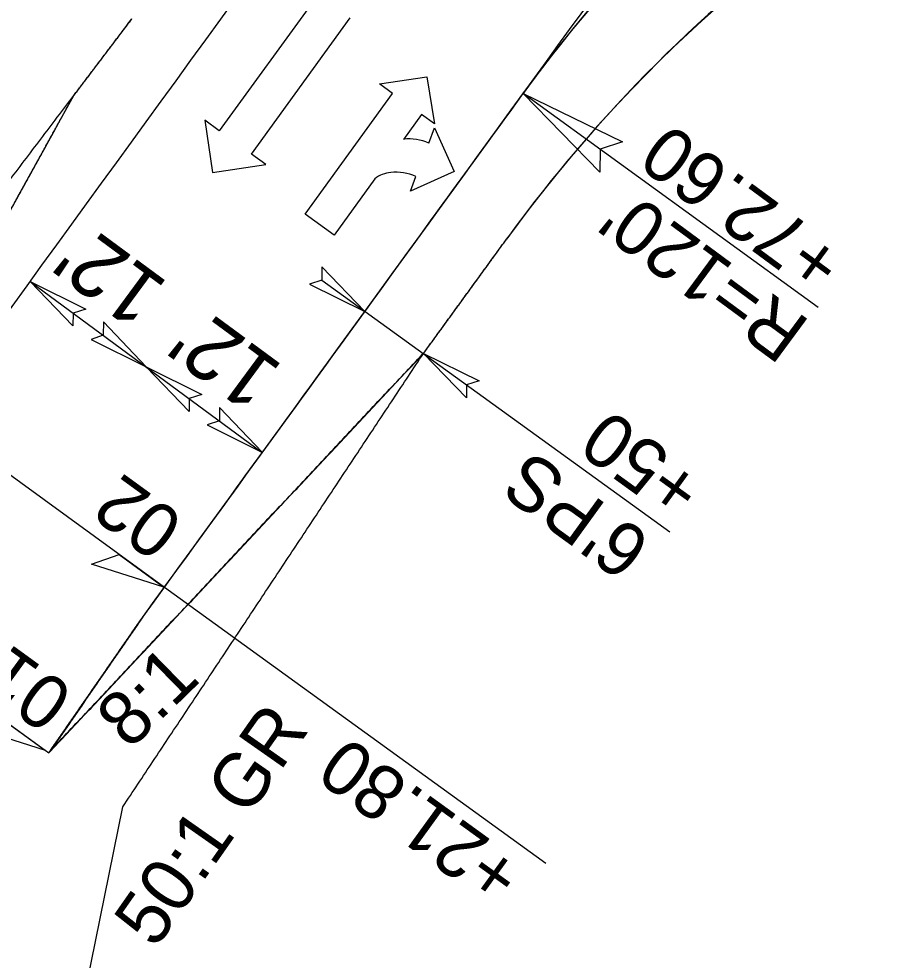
# Model space of a CAD drawing. Extents: x 1183930 to 1185370, y 573068 to 574871.
# Drawn here: x 1184246.9 to 1184319.5, y 573626.5 to 573704.9 of the extents above; entities that cross this region are included whole.
import ezdxf

# ---------------------------------------------------------------- set-up
doc = ezdxf.new("R2010")
doc.units = 0
for name, color, linetype in [('E_NCDOT_Terrain_Model_Contour_Minor', 7, 'Continuous'), ('E_NCDOT_Vertical_Profile_Ground_Line', 7, 'Continuous'), ('P_NCDOT_Horizontal_Alignment', 7, 'Continuous'), ('P_NCDOT_Horizontal_Alignment_Tick_Large', 7, 'Continuous'), ('PC_BEAM', 7, 'Continuous'), ('PC_COLUMN', 7, 'Continuous'), ('PC_OBJECT', 7, 'Continuous'), ('PC_PADFOOTING', 7, 'Continuous'), ('PC_SLAB', 7, 'Continuous')]:
    doc.layers.add(name, color=color, linetype=linetype)

msp = doc.modelspace()

# ---------------------------------------------------------------- linework, layer by layer
for points in [[(1184271.098, 573682.806), (1184275.711, 573680.544), (1184272.115, 573684.258), (1184272.111, 573683.15)], [(1184251.415, 573679.329), (1184247.856, 573683.034), (1184252.488, 573680.739), (1184251.434, 573680.398)], [(1184252.924, 573678.216), (1184257.517, 573675.915), (1184253.953, 573679.66), (1184253.94, 573678.551)], [(1184284.161, 573673.352), (1184280.571, 573677.026), (1184285.223, 573674.77), (1184284.171, 573674.421)], [(1184261.076, 573672.211), (1184257.517, 573675.915), (1184262.149, 573673.62), (1184261.095, 573673.28)], [(1184262.585, 573671.098), (1184267.178, 573668.797), (1184263.614, 573672.541), (1184263.601, 573671.433)]]:
    msp.add_lwpolyline(points, close=True)
at = {"layer": 'E_NCDOT_Terrain_Model_Contour_Minor'}
msp.add_line((1184313.426, 573680.866), (1184288.878, 573698.681), dxfattribs=at)
msp.add_lwpolyline([(1184295.251, 573692.14), (1184288.878, 573698.681), (1184297.142, 573694.66), (1184295.272, 573694.041)], close=True, dxfattribs=at)
at = {"layer": 'E_NCDOT_Vertical_Profile_Ground_Line'}
msp.add_arc((1184384.592, 573616.049), 120, 94.52634, 144.0215, dxfattribs=at)
for points in [[(1184251.486, 573698.511), (1184251.567, 573698.617), (1184251.728, 573698.83), (1184251.969, 573699.149), (1184252.211, 573699.468), (1184252.452, 573699.788), (1184252.694, 573700.107), (1184252.936, 573700.426), (1184253.177, 573700.745), (1184253.419, 573701.065), (1184253.661, 573701.384), (1184253.902, 573701.703), (1184254.144, 573702.022), (1184254.385, 573702.341), (1184254.627, 573702.661), (1184254.869, 573702.98), (1184255.11, 573703.299), (1184255.352, 573703.618), (1184255.593, 573703.938), (1184255.835, 573704.257), (1184256.077, 573704.576), (1184256.238, 573704.789), (1184256.318, 573704.895)], [(1184251.486, 573698.511), (1184251.567, 573698.617), (1184251.728, 573698.83), (1184251.969, 573699.149), (1184252.211, 573699.468), (1184252.452, 573699.788), (1184252.694, 573700.107), (1184252.936, 573700.426), (1184253.177, 573700.745), (1184253.419, 573701.065), (1184253.661, 573701.384), (1184253.902, 573701.703), (1184254.144, 573702.022), (1184254.385, 573702.341), (1184254.627, 573702.661), (1184254.869, 573702.98), (1184255.11, 573703.299), (1184255.352, 573703.618), (1184255.593, 573703.938), (1184255.835, 573704.257), (1184256.077, 573704.576), (1184256.238, 573704.789), (1184256.318, 573704.895)], [(1184251.486, 573698.511), (1184251.567, 573698.617), (1184251.728, 573698.83), (1184251.969, 573699.149), (1184252.211, 573699.468), (1184252.452, 573699.788), (1184252.694, 573700.107), (1184252.936, 573700.426), (1184253.177, 573700.745), (1184253.419, 573701.065), (1184253.661, 573701.384), (1184253.902, 573701.703), (1184254.144, 573702.022), (1184254.385, 573702.341), (1184254.627, 573702.661), (1184254.869, 573702.98), (1184255.11, 573703.299), (1184255.352, 573703.618), (1184255.593, 573703.938), (1184255.835, 573704.257), (1184256.077, 573704.576), (1184256.238, 573704.789), (1184256.318, 573704.895)], [(1184229.343, 573658.378), (1184229.712, 573659.047), (1184230.451, 573660.384), (1184231.559, 573662.391), (1184232.666, 573664.397), (1184233.774, 573666.404), (1184234.881, 573668.41), (1184235.989, 573670.417), (1184237.096, 573672.423), (1184238.203, 573674.43), (1184239.311, 573676.436), (1184240.418, 573678.443), (1184241.525, 573680.45), (1184242.632, 573682.456), (1184243.739, 573684.463), (1184244.846, 573686.47), (1184245.953, 573688.477), (1184247.06, 573690.483), (1184248.166, 573692.49), (1184249.273, 573694.497), (1184250.379, 573696.504), (1184251.117, 573697.842), (1184251.486, 573698.511)], [(1184229.343, 573658.378), (1184229.712, 573659.047), (1184230.451, 573660.384), (1184231.559, 573662.391), (1184232.666, 573664.397), (1184233.774, 573666.404), (1184234.881, 573668.41), (1184235.989, 573670.417), (1184237.096, 573672.423), (1184238.203, 573674.43), (1184239.311, 573676.436), (1184240.418, 573678.443), (1184241.525, 573680.45), (1184242.632, 573682.456), (1184243.739, 573684.463), (1184244.846, 573686.47), (1184245.953, 573688.477), (1184247.06, 573690.483), (1184248.166, 573692.49), (1184249.273, 573694.497), (1184250.379, 573696.504), (1184251.117, 573697.842), (1184251.486, 573698.511)], [(1184229.343, 573658.378), (1184229.712, 573659.047), (1184230.451, 573660.384), (1184231.559, 573662.391), (1184232.666, 573664.397), (1184233.774, 573666.404), (1184234.881, 573668.41), (1184235.989, 573670.417), (1184237.096, 573672.423), (1184238.203, 573674.43), (1184239.311, 573676.436), (1184240.418, 573678.443), (1184241.525, 573680.45), (1184242.632, 573682.456), (1184243.739, 573684.463), (1184244.846, 573686.47), (1184245.953, 573688.477), (1184247.06, 573690.483), (1184248.166, 573692.49), (1184249.273, 573694.497), (1184250.379, 573696.504), (1184251.117, 573697.842), (1184251.486, 573698.511)], [(1184280.571, 573677.026), (1184280.686, 573677.185), (1184280.917, 573677.502), (1184281.263, 573677.978), (1184281.608, 573678.454), (1184281.954, 573678.93), (1184282.3, 573679.406), (1184282.645, 573679.882), (1184282.991, 573680.358), (1184283.337, 573680.834), (1184283.682, 573681.31), (1184284.028, 573681.786), (1184284.373, 573682.262), (1184284.719, 573682.738), (1184285.065, 573683.214), (1184285.41, 573683.69), (1184285.756, 573684.166), (1184286.102, 573684.642), (1184286.447, 573685.118), (1184286.793, 573685.594), (1184287.138, 573686.07), (1184287.369, 573686.388), (1184287.484, 573686.547)], [(1184280.571, 573677.026), (1184280.686, 573677.185), (1184280.917, 573677.502), (1184281.263, 573677.978), (1184281.608, 573678.454), (1184281.954, 573678.93), (1184282.3, 573679.406), (1184282.645, 573679.882), (1184282.991, 573680.358), (1184283.337, 573680.834), (1184283.682, 573681.31), (1184284.028, 573681.786), (1184284.373, 573682.262), (1184284.719, 573682.738), (1184285.065, 573683.214), (1184285.41, 573683.69), (1184285.756, 573684.166), (1184286.102, 573684.642), (1184286.447, 573685.118), (1184286.793, 573685.594), (1184287.138, 573686.07), (1184287.369, 573686.388), (1184287.484, 573686.547)], [(1184249.41, 573643.786), (1184249.929, 573644.34), (1184250.968, 573645.448), (1184252.527, 573647.109), (1184254.085, 573648.771), (1184255.644, 573650.432), (1184257.202, 573652.094), (1184258.76, 573653.756), (1184260.318, 573655.418), (1184261.877, 573657.079), (1184263.435, 573658.741), (1184264.993, 573660.403), (1184266.551, 573662.065), (1184268.109, 573663.727), (1184269.667, 573665.39), (1184271.225, 573667.052), (1184272.783, 573668.714), (1184274.34, 573670.376), (1184275.898, 573672.039), (1184277.456, 573673.701), (1184279.014, 573675.364), (1184280.052, 573676.472), (1184280.571, 573677.026)], [(1184249.41, 573643.786), (1184249.929, 573644.34), (1184250.968, 573645.448), (1184252.527, 573647.109), (1184254.085, 573648.771), (1184255.644, 573650.432), (1184257.202, 573652.094), (1184258.76, 573653.756), (1184260.318, 573655.418), (1184261.877, 573657.079), (1184263.435, 573658.741), (1184264.993, 573660.403), (1184266.551, 573662.065), (1184268.109, 573663.727), (1184269.667, 573665.39), (1184271.225, 573667.052), (1184272.783, 573668.714), (1184274.34, 573670.376), (1184275.898, 573672.039), (1184277.456, 573673.701), (1184279.014, 573675.364), (1184280.052, 573676.472), (1184280.571, 573677.026)]]:
    msp.add_open_spline(points, degree=3, dxfattribs=at)
at = {"layer": 'P_NCDOT_Horizontal_Alignment'}
msp.add_line((1184229.343, 573658.378), (1184249.41, 573643.786), dxfattribs=at)
for centre, radius, start, end in [((1124762.272, 616900.028), 73527.16, 323.98763727, 324.09287436), ((1124762.272, 616900.028), 73527.16, 323.98763727, 324.09287436), ((1184385.997, 573628.197), 120, 94.52634, 144.02979), ((1184385.997, 573628.197), 120, 94.52634, 144.02979), ((1124762.272, 616900.028), 73551.16, 323.98763727, 324.06939248), ((1124762.272, 616900.028), 73551.16, 323.98763727, 324.02978658), ((1124762.272, 616900.028), 73551.16, 323.98763727, 324.02978658)]:
    msp.add_arc(centre, radius, start, end, dxfattribs=at)
msp.add_open_spline([(1184249.41, 573643.786), (1184249.538, 573643.971), (1184249.793, 573644.342), (1184250.177, 573644.898), (1184250.561, 573645.454), (1184250.944, 573646.009), (1184251.328, 573646.565), (1184251.711, 573647.121), (1184252.095, 573647.677), (1184252.479, 573648.233), (1184252.862, 573648.788), (1184253.246, 573649.344), (1184253.629, 573649.9), (1184254.013, 573650.456), (1184254.396, 573651.012), (1184254.78, 573651.567), (1184255.163, 573652.123), (1184255.547, 573652.679), (1184255.931, 573653.235), (1184256.314, 573653.791), (1184256.698, 573654.347), (1184256.953, 573654.717), (1184257.081, 573654.902)], degree=3, dxfattribs=at)
msp.add_open_spline([(1184249.41, 573643.786), (1184249.538, 573643.971), (1184249.793, 573644.342), (1184250.177, 573644.898), (1184250.561, 573645.454), (1184250.944, 573646.009), (1184251.328, 573646.565), (1184251.711, 573647.121), (1184252.095, 573647.677), (1184252.479, 573648.233), (1184252.862, 573648.788), (1184253.246, 573649.344), (1184253.629, 573649.9), (1184254.013, 573650.456), (1184254.396, 573651.012), (1184254.78, 573651.567), (1184255.163, 573652.123), (1184255.547, 573652.679), (1184255.931, 573653.235), (1184256.314, 573653.791), (1184256.698, 573654.347), (1184256.953, 573654.717), (1184257.081, 573654.902)], degree=3, dxfattribs=at)
at = {"layer": 'P_NCDOT_Horizontal_Alignment_Tick_Large'}
msp.add_arc((1184384.592, 573616.049), 120, 94.52634, 144.0215, dxfattribs=at)
msp.add_arc((1184384.592, 573616.049), 120, 94.52634, 144.0215, dxfattribs=at)
for points, degree in [([(1184251.486, 573698.511), (1184251.532, 573698.571), (1184251.69, 573698.781), (1184251.979, 573699.162), (1184252.208, 573699.465), (1184252.453, 573699.789), (1184252.694, 573700.107), (1184252.936, 573700.426), (1184253.177, 573700.745), (1184253.419, 573701.065), (1184253.661, 573701.384), (1184253.902, 573701.703), (1184254.144, 573702.022), (1184254.385, 573702.341), (1184254.627, 573702.661), (1184254.869, 573702.98), (1184255.11, 573703.299), (1184255.351, 573703.617), (1184255.596, 573703.941), (1184255.825, 573704.244), (1184256.114, 573704.625), (1184256.272, 573704.835), (1184256.318, 573704.895)], 2), ([(1184251.486, 573698.511), (1184251.532, 573698.571), (1184251.69, 573698.781), (1184251.979, 573699.162), (1184252.208, 573699.465), (1184252.453, 573699.789), (1184252.694, 573700.107), (1184252.936, 573700.426), (1184253.177, 573700.745), (1184253.419, 573701.065), (1184253.661, 573701.384), (1184253.902, 573701.703), (1184254.144, 573702.022), (1184254.385, 573702.341), (1184254.627, 573702.661), (1184254.869, 573702.98), (1184255.11, 573703.299), (1184255.351, 573703.617), (1184255.596, 573703.941), (1184255.825, 573704.244), (1184256.114, 573704.625), (1184256.272, 573704.835), (1184256.318, 573704.895)], 2), ([(1184224.019, 573662.249), (1184224.477, 573662.853), (1184225.393, 573664.061), (1184226.767, 573665.874), (1184228.141, 573667.687), (1184229.515, 573669.5), (1184230.888, 573671.313), (1184232.262, 573673.126), (1184233.635, 573674.939), (1184235.009, 573676.752), (1184236.382, 573678.565), (1184237.756, 573680.378), (1184239.129, 573682.191), (1184240.502, 573684.004), (1184241.875, 573685.817), (1184243.248, 573687.63), (1184244.621, 573689.444), (1184245.994, 573691.257), (1184247.367, 573693.07), (1184248.74, 573694.884), (1184250.113, 573696.697), (1184251.028, 573697.906), (1184251.486, 573698.511)], 3), ([(1184224.019, 573662.249), (1184224.477, 573662.853), (1184225.393, 573664.061), (1184226.767, 573665.874), (1184228.141, 573667.687), (1184229.515, 573669.5), (1184230.888, 573671.313), (1184232.262, 573673.126), (1184233.635, 573674.939), (1184235.009, 573676.752), (1184236.382, 573678.565), (1184237.756, 573680.378), (1184239.129, 573682.191), (1184240.502, 573684.004), (1184241.875, 573685.817), (1184243.248, 573687.63), (1184244.621, 573689.444), (1184245.994, 573691.257), (1184247.367, 573693.07), (1184248.74, 573694.884), (1184250.113, 573696.697), (1184251.028, 573697.906), (1184251.486, 573698.511)], 3), ([(1184280.571, 573677.026), (1184280.637, 573677.116), (1184280.864, 573677.429), (1184281.277, 573677.998), (1184281.604, 573678.449), (1184281.955, 573678.932), (1184282.299, 573679.406), (1184282.645, 573679.882), (1184282.991, 573680.358), (1184283.337, 573680.834), (1184283.682, 573681.31), (1184284.028, 573681.786), (1184284.373, 573682.262), (1184284.719, 573682.738), (1184285.065, 573683.214), (1184285.41, 573683.69), (1184285.756, 573684.167), (1184286.101, 573684.641), (1184286.451, 573685.124), (1184286.778, 573685.575), (1184287.192, 573686.144), (1184287.418, 573686.456), (1184287.484, 573686.547)], 2), ([(1184280.571, 573677.026), (1184280.637, 573677.116), (1184280.864, 573677.429), (1184281.277, 573677.998), (1184281.604, 573678.449), (1184281.955, 573678.932), (1184282.299, 573679.406), (1184282.645, 573679.882), (1184282.991, 573680.358), (1184283.337, 573680.834), (1184283.682, 573681.31), (1184284.028, 573681.786), (1184284.373, 573682.262), (1184284.719, 573682.738), (1184285.065, 573683.214), (1184285.41, 573683.69), (1184285.756, 573684.167), (1184286.101, 573684.641), (1184286.451, 573685.124), (1184286.778, 573685.575), (1184287.192, 573686.144), (1184287.418, 573686.456), (1184287.484, 573686.547)], 2), ([(1184255.57, 573639.307), (1184255.987, 573639.935), (1184256.821, 573641.192), (1184258.071, 573643.078), (1184259.322, 573644.964), (1184260.572, 573646.849), (1184261.823, 573648.735), (1184263.073, 573650.621), (1184264.323, 573652.507), (1184265.573, 573654.393), (1184266.824, 573656.279), (1184268.074, 573658.165), (1184269.324, 573660.051), (1184270.574, 573661.937), (1184271.824, 573663.823), (1184273.073, 573665.709), (1184274.323, 573667.595), (1184275.573, 573669.481), (1184276.823, 573671.367), (1184278.072, 573673.254), (1184279.322, 573675.14), (1184280.155, 573676.397), (1184280.571, 573677.026)], 3), ([(1184255.57, 573639.307), (1184255.987, 573639.935), (1184256.821, 573641.192), (1184258.071, 573643.078), (1184259.322, 573644.964), (1184260.572, 573646.849), (1184261.823, 573648.735), (1184263.073, 573650.621), (1184264.323, 573652.507), (1184265.573, 573654.393), (1184266.824, 573656.279), (1184268.074, 573658.165), (1184269.324, 573660.051), (1184270.574, 573661.937), (1184271.824, 573663.823), (1184273.073, 573665.709), (1184274.323, 573667.595), (1184275.573, 573669.481), (1184276.823, 573671.367), (1184278.072, 573673.254), (1184279.322, 573675.14), (1184280.155, 573676.397), (1184280.571, 573677.026)], 3)]:
    msp.add_open_spline(points, degree=degree, dxfattribs=at)
at = {"layer": 'PC_BEAM'}
for p, q in [((1184271.809, 573706.912), (1184263.588, 573695.581)), ((1184266.259, 573693.643), (1184274.48, 573704.974)), ((1184276.917, 573699.475), (1184280.85, 573700.073)), ((1184280.85, 573700.073), (1184281.51, 573696.151)), ((1184278.011, 573698.684), (1184276.917, 573699.475)), ((1184270.729, 573688.622), (1184278.011, 573698.684)), ((1184280.417, 573696.942), (1184278.913, 573694.864)), ((1184281.51, 573696.151), (1184280.417, 573696.942)), ((1184263.588, 573695.581), (1184262.374, 573696.462)), ((1184262.374, 573696.462), (1184263.033, 573692.092)), ((1184281.024, 573694.558), (1184281.498, 573695.826)), ((1184281.498, 573695.826), (1184283.144, 573692.191)), ((1184267.473, 573692.762), (1184266.259, 573693.643)), ((1184263.033, 573692.092), (1184267.473, 573692.762)), ((1184283.144, 573692.191), (1184279.508, 573690.545)), ((1184276.538, 573691.584), (1184273.135, 573686.881)), ((1184279.508, 573690.545), (1184279.955, 573691.777)), ((1184273.135, 573686.881), (1184270.729, 573688.622))]:
    msp.add_line(p, q, dxfattribs=at)
for centre, radius, start, end in [((1184279.378, 573690.912), 3.991, 65.6939, 96.5725), ((1184277.982, 573689.828), 2.272, 93.17619, 129.48818), ((1184278.319, 573688.133), 3.991, 65.81271, 96.66627)]:
    msp.add_arc(centre, radius, start, end, dxfattribs=at)
at = {"layer": 'PC_COLUMN'}
for points in [[(1184258.987, 573657.597), (1184252.958, 573659.508), (1184255.246, 573660.317)], [(1184249.137, 573643.985), (1184243.108, 573645.896), (1184245.396, 573646.705)]]:
    msp.add_lwpolyline(points, close=True, dxfattribs=at)
at = {"layer": 'PC_OBJECT'}
for centre, radius, start, end in [((1124762.272, 616900.028), 73527.16, 323.98763727, 324.09287436), ((1184386.112, 573628.356), 120, 94.52634, 144.02979), ((1184384.708, 573616.207), 120, 125.84259, 144.0215), ((1124762.388, 616900.186), 73551.16, 323.98763727, 324.02978658)]:
    msp.add_arc(centre, radius, start, end, dxfattribs=at)
for points in [[(1184251.486, 573698.511), (1184251.497, 573698.525), (1184251.508, 573698.54), (1184251.519, 573698.554), (1184251.664, 573698.747), (1184251.81, 573698.939), (1184251.955, 573699.131), (1184252.101, 573699.323), (1184252.246, 573699.515), (1184252.392, 573699.707), (1184252.537, 573699.899), (1184252.682, 573700.092), (1184252.828, 573700.284), (1184252.973, 573700.476), (1184253.119, 573700.668), (1184253.264, 573700.86), (1184253.41, 573701.052), (1184253.555, 573701.244), (1184253.701, 573701.437), (1184253.846, 573701.629), (1184253.991, 573701.821), (1184254.137, 573702.013), (1184254.282, 573702.205), (1184254.428, 573702.397), (1184254.573, 573702.59), (1184254.719, 573702.782), (1184254.864, 573702.974), (1184255.009, 573703.166), (1184255.155, 573703.358), (1184255.3, 573703.55), (1184255.446, 573703.742), (1184255.737, 573704.127), (1184256.027, 573704.511), (1184256.318, 573704.895)], [(1184244.108, 573685.132), (1184244.132, 573685.175), (1184244.156, 573685.219), (1184244.18, 573685.262), (1184244.277, 573685.438), (1184244.374, 573685.614), (1184244.471, 573685.789), (1184244.567, 573685.965), (1184244.664, 573686.141), (1184244.761, 573686.317), (1184244.858, 573686.492), (1184244.955, 573686.668), (1184245.052, 573686.844), (1184245.149, 573687.019), (1184245.246, 573687.195), (1184245.343, 573687.371), (1184245.44, 573687.547), (1184245.537, 573687.722), (1184245.634, 573687.898), (1184245.731, 573688.074), (1184245.828, 573688.25), (1184245.924, 573688.425), (1184246.021, 573688.601), (1184246.118, 573688.777), (1184246.215, 573688.953), (1184246.312, 573689.128), (1184246.409, 573689.304), (1184246.506, 573689.48), (1184246.603, 573689.655), (1184246.7, 573689.831), (1184246.797, 573690.007), (1184246.894, 573690.183), (1184246.991, 573690.358), (1184247.088, 573690.534), (1184247.184, 573690.71), (1184247.281, 573690.886), (1184247.378, 573691.061), (1184247.475, 573691.237), (1184247.572, 573691.413), (1184247.669, 573691.589), (1184247.766, 573691.764), (1184247.863, 573691.94), (1184247.96, 573692.116), (1184248.057, 573692.292), (1184248.154, 573692.467), (1184248.25, 573692.643), (1184248.347, 573692.819), (1184248.444, 573692.995), (1184248.541, 573693.17), (1184248.638, 573693.346), (1184248.735, 573693.522), (1184248.832, 573693.697), (1184248.929, 573693.873), (1184249.026, 573694.049), (1184249.123, 573694.225), (1184249.22, 573694.4), (1184249.316, 573694.576), (1184249.413, 573694.752), (1184249.51, 573694.928), (1184249.607, 573695.103), (1184249.704, 573695.279), (1184249.801, 573695.455), (1184249.898, 573695.631), (1184249.995, 573695.806), (1184250.092, 573695.982), (1184250.189, 573696.158), (1184250.285, 573696.334), (1184250.686, 573697.059), (1184251.086, 573697.785), (1184251.486, 573698.511)], [(1184280.686, 573677.185), (1184280.802, 573677.343), (1184281.032, 573677.661), (1184281.378, 573678.137), (1184281.723, 573678.613), (1184282.069, 573679.089), (1184282.415, 573679.565), (1184282.76, 573680.041), (1184283.106, 573680.517), (1184283.452, 573680.993), (1184283.797, 573681.469), (1184284.143, 573681.945), (1184284.489, 573682.421), (1184284.834, 573682.897), (1184285.18, 573683.373), (1184285.525, 573683.849), (1184285.871, 573684.325), (1184286.217, 573684.801), (1184286.562, 573685.277), (1184286.908, 573685.753), (1184287.253, 573686.229), (1184287.484, 573686.546), (1184287.599, 573686.705)], [(1184249.525, 573643.945), (1184250.044, 573644.498), (1184251.083, 573645.606), (1184252.642, 573647.268), (1184254.2, 573648.929), (1184255.759, 573650.591), (1184257.317, 573652.253), (1184258.875, 573653.914), (1184260.434, 573655.576), (1184261.992, 573657.238), (1184263.55, 573658.9), (1184265.108, 573660.562), (1184266.666, 573662.224), (1184268.224, 573663.886), (1184269.782, 573665.548), (1184271.34, 573667.21), (1184272.898, 573668.873), (1184274.456, 573670.535), (1184276.013, 573672.197), (1184277.571, 573673.86), (1184279.129, 573675.522), (1184280.167, 573676.63), (1184280.686, 573677.185)], [(1184257.196, 573655.061), (1184257.068, 573654.876), (1184256.813, 573654.505), (1184256.429, 573653.949), (1184256.046, 573653.393), (1184255.662, 573652.838), (1184255.279, 573652.282), (1184254.895, 573651.726), (1184254.511, 573651.17), (1184254.128, 573650.614), (1184253.744, 573650.058), (1184253.361, 573649.503), (1184252.977, 573648.947), (1184252.594, 573648.391), (1184252.21, 573647.835), (1184251.827, 573647.279), (1184251.443, 573646.724), (1184251.059, 573646.168), (1184250.676, 573645.612), (1184250.292, 573645.056), (1184249.909, 573644.5), (1184249.653, 573644.13), (1184249.525, 573643.945)]]:
    msp.add_open_spline(points, degree=3, dxfattribs=at)
at = {"layer": 'PC_PADFOOTING'}
for p, q in [((1184247.856, 573683.034), (1184267.169, 573668.804)), ((1184272.111, 573683.15), (1184301.065, 573662.193)), ((1184259.03, 573657.583), (1184290.76, 573634.617))]:
    msp.add_line(p, q, dxfattribs=at)
msp.add_lwpolyline([(1184249.159, 573607.728), (1184255.57, 573639.307)], dxfattribs=at)
at = {"layer": 'PC_SLAB'}
msp.add_line((1184259.021, 573657.572), (1184239.608, 573671.682), dxfattribs=at)

# ---------------------------------------------------------------- texts
at = {"layer": 'E_NCDOT_Terrain_Model_Contour_Minor'}
for s, p in [('+72.60', (1184315.887, 573685.31)), ("R=120'", (1184312.896, 573679.644))]:
    msp.add_text(s, height=4.5, rotation=143.59171, dxfattribs=at).set_placement(p)
at = {"layer": 'PC_PADFOOTING'}
for s, height, rotation, p in [("12'", 5, 143.61788, (1184259.468, 573682.849)), ("12'", 5, 143.61788, (1184269.026, 573675.931)), ('+50', 4.5, 144.10304, (1184304.207, 573666.544)), ('PS', 4.5, 144.10304, (1184295.971, 573664.375)), ("6'", 4.5, 144.10304, (1184299.733, 573661.572)), ('8:1', 4.5, 44.30204, (1184256.131, 573643.968)), ('50:1 GR', 4.5, 54.95798, (1184258.265, 573627.391)), ('+21.80', 4.5, 144.10304, (1184289.167, 573634.406))]:
    msp.add_text(s, height=height, rotation=rotation, dxfattribs=at).set_placement(p)
at = {"layer": 'PC_SLAB'}
for s, p in [('02', (1184260.847, 573663.234)), ('015', (1184251.669, 573648.918))]:
    msp.add_text(s, height=4.5, rotation=143.97712, dxfattribs=at).set_placement(p)

doc.saveas('drawing.dxf')
